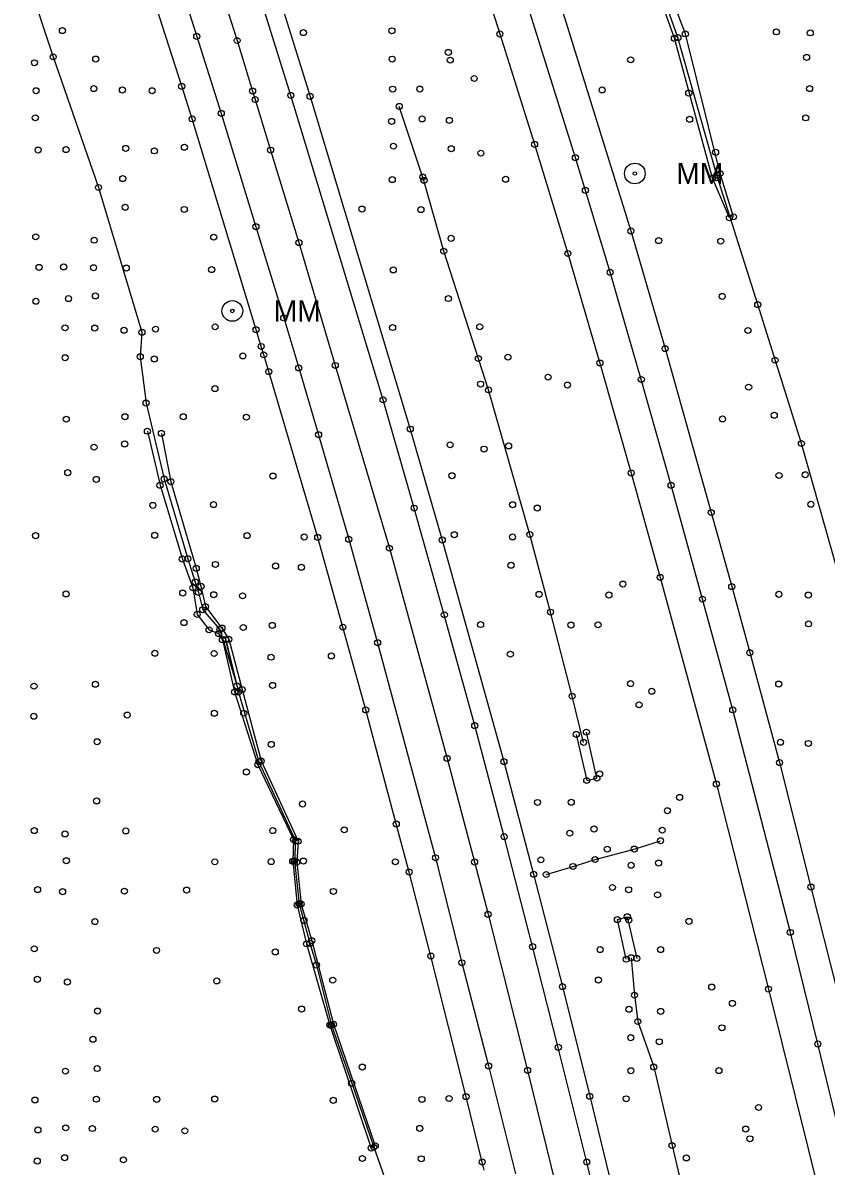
# Model space of a CAD drawing. Extents: x 20503438 to 20508873, y 7964251 to 7984667.
# Drawn here: x 20506329.2 to 20506595.4, y 7974717.9 to 7975096.9 of the extents above; entities that cross this region are included whole.
import ezdxf

# ---------------------------------------------------------------- set-up
doc = ezdxf.new("R2010")
doc.units = 0
for name, color, linetype in [('SurBreakLine', 7, 'Continuous'), ('SurConcreteSlab', 7, 'Continuous'), ('SurDrainageArrowDown', 7, 'Continuous'), ('SurDrainageArrowUp', 7, 'Continuous'), ('SurEdgeRoadPaved', 7, 'Continuous'), ('SurEdgeShoulderPaved', 7, 'Continuous'), ('SurPointsNonDTM', 7, 'Continuous'), ('SurRoadPoints', 7, 'Continuous'), ('SurSurveyPoints', 7, 'Continuous')]:
    doc.layers.add(name, color=color, linetype=linetype)

msp = doc.modelspace()

# ---------------------------------------------------------------- linework, layer by layer
at = {"layer": 'SurBreakLine'}
for points in [[(20506349.14, 7975482.98), (20506362.94, 7975447.73), (20506373.06, 7975421.29), (20506389.9, 7975376.81), (20506416.68, 7975304.59), (20506442.42, 7975230.98), (20506465.81, 7975160.63), (20506487.25, 7975093.26), (20506498.75, 7975056.68), (20506509.78, 7975020.48), (20506520.41, 7974984.15), (20506530.78, 7974947.69), (20506540.38, 7974913.1), (20506559, 7974844.57), (20506576.27, 7974776.6), (20506593.8, 7974705.89)], [(20506563.33, 7975032.31), (20506557.73, 7975045.49), (20506545.09, 7975091.83), (20506536.07, 7975117.23), (20506528.64, 7975137.21), (20506513.06, 7975181.68), (20506498.04, 7975232.83), (20506490.75, 7975254.66), (20506483.47, 7975281.58), (20506478.73, 7975292.65), (20506472.08, 7975308.47), (20506471.96, 7975323.59)], [(20506564.68, 7975032.65), (20506560.23, 7975047), (20506548.72, 7975093.3), (20506540.37, 7975115.26), (20506533.76, 7975140.2), (20506518.04, 7975183.5), (20506500.13, 7975235.89), (20506493.28, 7975255.12), (20506484.64, 7975281.71), (20506485.6, 7975286.88), (20506482.64, 7975294.9), (20506475.18, 7975312.04), (20506473.09, 7975324.52)], [(20506389.28, 7975125.26), (20506400.17, 7975091.1), (20506405.3, 7975074.33), (20506406.15, 7975071.53), (20506411.27, 7975054.76), (20506420.66, 7975024.09), (20506432.71, 7974983.37), (20506450.65, 7974922.79), (20506469.75, 7974853.08), (20506478.86, 7974818.75), (20506483.33, 7974801.41), (20506496.44, 7974749.65), (20506513.28, 7974680.82)], [(20506370.42, 7974961.57), (20506374.61, 7974943.64), (20506382.01, 7974919.2), (20506385.5, 7974909.64), (20506386.94, 7974900.83), (20506390.87, 7974895.72), (20506394.03, 7974894.48), (20506395.3, 7974892.44), (20506399.35, 7974875.13), (20506407.04, 7974851), (20506418.84, 7974826.2), (20506418.61, 7974818.98), (20506420.12, 7974804.45), (20506423.15, 7974791.61), (20506430.93, 7974764.69), (20506444.62, 7974723.91)], [(20506375.08, 7974960.84), (20506378.21, 7974944.81), (20506386.64, 7974916.14), (20506388.19, 7974910.14), (20506389.67, 7974903.41), (20506395.13, 7974896.31), (20506397.4, 7974892.6), (20506401.84, 7974875.91), (20506408.1, 7974852.25), (20506420.39, 7974825.64), (20506419.97, 7974818.7), (20506421.36, 7974804.8), (20506424.88, 7974792.66), (20506432.12, 7974764.97), (20506445.95, 7974724.65)], [(20506502.61, 7974814.6), (20506511.49, 7974817.27), (20506518.79, 7974819.57), (20506531.8, 7974823.05), (20506540.49, 7974825.8)]]:
    msp.add_lwpolyline(points, dxfattribs=at)
at = {"layer": 'SurConcreteSlab'}
for points in [[(20506512.57, 7974861.04), (20506516.05, 7974845.77), (20506519.41, 7974846.53), (20506515.93, 7974861.8)], [(20506529.15, 7974786.52), (20506526.21, 7974799.66), (20506529.49, 7974800.59), (20506532.6, 7974786.79)]]:
    msp.add_lwpolyline(points, dxfattribs=at)
at = {"layer": 'SurDrainageArrowDown'}
for points in [[(20506657.71, 7974715.84), (20506642.35, 7974760.13), (20506632.42, 7974809.79), (20506615.88, 7974859.7), (20506600.79, 7974909.51), (20506587.18, 7974957.49), (20506572.7, 7975003.54), (20506559.2, 7975046.45), (20506546.26, 7975092.07), (20506538.01, 7975115.31)], [(20506514.97, 7974858.39), (20506511.2, 7974873.72), (20506504.04, 7974901.59), (20506497.18, 7974927.32), (20506483.49, 7974975.27), (20506468.65, 7975021.25), (20506462.1, 7975044.71), (20506453.91, 7975069.27)]]:
    msp.add_lwpolyline(points, dxfattribs=at)
at = {"layer": 'SurDrainageArrowUp'}
for points in [[(20506330.76, 7975111.05), (20506339.21, 7975085.68), (20506354.22, 7975042.36), (20506368.61, 7974994.38), (20506368.05, 7974986.26), (20506369.98, 7974970.9), (20506375.98, 7974945.73), (20506383.84, 7974919.28), (20506386.3, 7974911.54), (20506387.33, 7974908.1), (20506388.76, 7974902.36), (20506394.43, 7974895.84), (20506400.13, 7974877.07), (20506396.37, 7974892.43), (20506400.64, 7974875.1), (20506407.39, 7974851.97), (20506419.55, 7974825.72), (20506419.14, 7974819.06), (20506420.69, 7974804.93), (20506424.29, 7974791.81), (20506426.47, 7974784.56), (20506431.41, 7974764.69), (20506438.13, 7974745.38), (20506445.47, 7974724.2), (20506449.66, 7974712.24)], [(20506530.75, 7974787.02), (20506531.86, 7974774.59), (20506532.96, 7974765.86), (20506538.23, 7974750.79), (20506544.31, 7974724.75), (20506550.52, 7974698.23), (20506555.49, 7974671.16), (20506562.9, 7974645.49), (20506569.02, 7974618.1), (20506580.96, 7974569.62)]]:
    msp.add_lwpolyline(points, dxfattribs=at)
at = {"layer": 'SurEdgeRoadPaved'}
for points in [[(20506532.64, 7974648.96), (20506516.06, 7974719.27), (20506506.62, 7974757.3), (20506498.09, 7974790.71), (20506488.67, 7974827.17), (20506478.91, 7974863.97), (20506468.84, 7974900.69), (20506458.86, 7974936.07), (20506448.53, 7974971.96), (20506417.96, 7975072.9), (20506405.34, 7975113.32), (20506382.6, 7975182.03), (20506369.4, 7975220.83), (20506345.88, 7975288.32), (20506331.62, 7975327.71), (20506320.36, 7975358.51), (20506306.95, 7975393.79), (20506278.91, 7975465.84), (20506257.71, 7975518.12)], [(20506367.4, 7975497.02), (20506382.84, 7975458.29), (20506396.34, 7975422.39), (20506402.33, 7975406.46), (20506419.54, 7975360.34), (20506427.81, 7975337.94), (20506435.05, 7975318.28), (20506442.77, 7975296.67), (20506447.6, 7975283.16), (20506459.75, 7975248.31), (20506474.87, 7975203.27), (20506484.19, 7975175.26), (20506494.28, 7975143.45), (20506508.53, 7975099.05), (20506530.67, 7975027.95), (20506542.03, 7974988.95), (20506557.31, 7974934.61), (20506564.1, 7974910.06), (20506570.08, 7974888.15), (20506579.93, 7974851.7), (20506590.35, 7974810.45), (20506601.11, 7974767.59), (20506615.26, 7974710.46)], [(20506247.96, 7975479.81), (20506260.54, 7975448.2), (20506275.43, 7975410.2), (20506290.26, 7975371.02), (20506301.37, 7975341.22), (20506312.67, 7975310.54), (20506324.74, 7975277.04), (20506349.3, 7975206.77), (20506372.83, 7975136.5), (20506386.78, 7975092.48), (20506394.92, 7975066.92), (20506406.39, 7975029.37), (20506415.61, 7974999.14), (20506420.57, 7974982.55), (20506427.17, 7974960.41), (20506437.15, 7974925.73), (20506446.74, 7974891.45), (20506465.93, 7974820.14), (20506474.65, 7974785.33), (20506483.51, 7974751.12), (20506492.4, 7974715.32)], [(20506618.24, 7974651.55), (20506601.4, 7974722.56), (20506592.63, 7974758.41), (20506583.52, 7974795.39), (20506564.42, 7974869.18), (20506554.39, 7974905.89), (20506543.98, 7974943.66), (20506534.13, 7974978.72), (20506523.8, 7975014.27), (20506515.58, 7975041.4), (20506512.29, 7975052.25), (20506490.77, 7975121.09), (20506467.72, 7975192.09), (20506455.87, 7975227.47), (20506443.11, 7975264.71), (20506430.35, 7975301.25), (20506417.72, 7975336.15), (20506403.48, 7975374.04), (20506389.38, 7975412.58), (20506375.71, 7975448.39), (20506362.64, 7975481.5)], [(20506482.06, 7974716.57), (20506481.39, 7974719.26), (20506476.04, 7974740.93), (20506464.38, 7974787.55), (20506457.19, 7974815.4), (20506452.9, 7974831.37), (20506442.78, 7974869.15), (20506435.21, 7974896.61), (20506426.88, 7974926.37), (20506410.66, 7974981.33), (20506408.98, 7974986.89), (20506408.14, 7974989.67), (20506406.46, 7974995.22), (20506385.25, 7975065.12), (20506381.79, 7975075.91), (20506371.23, 7975109.03)]]:
    msp.add_lwpolyline(points, dxfattribs=at)
at = {"layer": 'SurEdgeShoulderPaved'}
msp.add_lwpolyline([(20506267.06, 7975511.74), (20506296.53, 7975437.96), (20506310.81, 7975400.98), (20506324.27, 7975365.52), (20506351.09, 7975291.82), (20506363.94, 7975255.58), (20506381.4, 7975204.73), (20506388.98, 7975182.4), (20506412.98, 7975109.14), (20506424.35, 7975072.59), (20506457.56, 7974962.26), (20506468.15, 7974925.5), (20506488.59, 7974852.02), (20506498.44, 7974814.69), (20506507.99, 7974777.45), (20506517.02, 7974741.08), (20506525.96, 7974704.19)], dxfattribs=at)
at = {"layer": 'SurPointsNonDTM'}
msp.add_circle((20506522.84, 7974823.01), 1, dxfattribs=at)
at = {"layer": 'SurRoadPoints'}
for centre, radius in [((20506531.98, 7975047.01), 3.43), ((20506531.98, 7975047.01), 0.571), ((20506398.58, 7975001.43), 3.43), ((20506398.58, 7975001.43), 0.571)]:
    msp.add_circle(centre, radius, dxfattribs=at)
at = {"layer": 'SurSurveyPoints'}
for centre in [(20506342.27, 7975094.38), (20506386.78, 7975092.48), (20506422.12, 7975093.72), (20506451.46, 7975094.32), (20506487.25, 7975093.26), (20506545.09, 7975091.83), (20506546.26, 7975092.07), (20506548.72, 7975093.3), (20506578.9, 7975093.96), (20506590.12, 7975093.63), (20506400.17, 7975091.1), (20506333, 7975083.71), (20506339.21, 7975085.68), (20506353.29, 7975084.95), (20506451.54, 7975084.93), (20506470.17, 7975087.17), (20506470.82, 7975084.59), (20506530.6, 7975084.7), (20506588.91, 7975085.5), (20506478.74, 7975078.51), (20506333.56, 7975074.46), (20506352.67, 7975075.16), (20506362.15, 7975074.69), (20506372, 7975074.44), (20506381.79, 7975075.91), (20506405.3, 7975074.33), (20506417.96, 7975072.9), (20506424.35, 7975072.59), (20506451.72, 7975074.98), (20506460.71, 7975075), (20506521.14, 7975074.72), (20506549.84, 7975073.66), (20506589.89, 7975075.16), (20506406.15, 7975071.53), (20506453.91, 7975069.27), (20506333.29, 7975065.47), (20506385.25, 7975065.12), (20506394.92, 7975066.92), (20506461.48, 7975065.11), (20506550.13, 7975064.98), (20506588.63, 7975065.45), (20506451.36, 7975064.29), (20506470.53, 7975064.62), (20506334.22, 7975054.77), (20506343.48, 7975054.93), (20506363.25, 7975055.33), (20506372.74, 7975054.51), (20506382.7, 7975055.7), (20506411.27, 7975054.76), (20506451.99, 7975056.06), (20506471.14, 7975055.21), (20506480.95, 7975053.76), (20506498.75, 7975056.68), (20506558.74, 7975054.02), (20506512.29, 7975052.25), (20506461.71, 7975045.83), (20506559.2, 7975046.45), (20506560.23, 7975047), (20506354.22, 7975042.36), (20506362.25, 7975045.33), (20506451.6, 7975044.98), (20506462.1, 7975044.71), (20506489.16, 7975045.09), (20506557.73, 7975045.49), (20506559.03, 7975045.59), (20506515.58, 7975041.4), (20506363.07, 7975035.8), (20506382.66, 7975035.09), (20506441.52, 7975035.22), (20506461.1, 7975035.03), (20506563.33, 7975032.31), (20506564.68, 7975032.65), (20506406.39, 7975029.37), (20506530.67, 7975027.95), (20506333.43, 7975026.01), (20506352.8, 7975024.89), (20506392.4, 7975025.91), (20506420.66, 7975024.09), (20506471.1, 7975025.51), (20506539.88, 7975024.75), (20506560.45, 7975024.57), (20506468.65, 7975021.25), (20506509.78, 7975020.48), (20506334.53, 7975015.87), (20506342.68, 7975016.02), (20506352.58, 7975015.76), (20506363.44, 7975015.65), (20506391.73, 7975015.15), (20506451.92, 7975015.03), (20506523.8, 7975014.27), (20506333.46, 7975004.64), (20506344.28, 7975005.53), (20506353.2, 7975006.41), (20506470.19, 7975005.55), (20506560.94, 7975006.25), (20506572.7, 7975003.54), (20506415.61, 7974999.14), (20506343.12, 7974995.83), (20506352.97, 7974995.75), (20506362.71, 7974995.03), (20506368.61, 7974994.38), (20506373.12, 7974995.41), (20506392.88, 7974996.18), (20506406.46, 7974995.22), (20506451.7, 7974995.94), (20506480.58, 7974996.18), (20506569.45, 7974994.96), (20506408.14, 7974989.67), (20506542.03, 7974988.95), (20506343.17, 7974985.92), (20506368.05, 7974986.26), (20506372.69, 7974985.54), (20506402.07, 7974986.54), (20506408.98, 7974986.89), (20506480.12, 7974985.67), (20506489.92, 7974986.12), (20506420.57, 7974982.55), (20506432.71, 7974983.37), (20506520.41, 7974984.15), (20506578.46, 7974985.12), (20506410.66, 7974981.33), (20506503.25, 7974979.49), (20506534.13, 7974978.72), (20506392.8, 7974975.68), (20506480.87, 7974977.18), (20506483.49, 7974975.27), (20506509.65, 7974976.86), (20506569.71, 7974976.17), (20506369.98, 7974970.9), (20506448.53, 7974971.96), (20506362.99, 7974966.36), (20506382.32, 7974966.36), (20506403.25, 7974966.22), (20506578.19, 7974966.85), (20506343.54, 7974965.55), (20506561.05, 7974965.63), (20506370.42, 7974961.57), (20506375.08, 7974960.84), (20506427.17, 7974960.41), (20506457.56, 7974962.26), (20506352.75, 7974956.28), (20506362.9, 7974957.34), (20506470.76, 7974957.06), (20506482.02, 7974955.63), (20506490.15, 7974956.69), (20506587.18, 7974957.49), (20506344.03, 7974947.82), (20506530.78, 7974947.69), (20506353.47, 7974945.6), (20506374.61, 7974943.64), (20506375.98, 7974945.73), (20506378.21, 7974944.81), (20506412.04, 7974946.7), (20506471.37, 7974946.81), (20506543.98, 7974943.66), (20506579.76, 7974946.89), (20506588.45, 7974947.15), (20506372.23, 7974936.97), (20506392.35, 7974937.24), (20506458.86, 7974936.07), (20506491.46, 7974937.18), (20506499.63, 7974936.08), (20506590.32, 7974937.36), (20506557.31, 7974934.61), (20506333.38, 7974926.94), (20506372.86, 7974927.06), (20506403.47, 7974926.96), (20506422.4, 7974926.49), (20506426.88, 7974926.37), (20506437.15, 7974925.73), (20506468.15, 7974925.5), (20506472.15, 7974927.26), (20506491.44, 7974926.52), (20506497.18, 7974927.32), (20506450.65, 7974922.79), (20506382.01, 7974919.2), (20506383.84, 7974919.28), (20506392.98, 7974917.39), (20506490.94, 7974917.13), (20506386.64, 7974916.14), (20506412.92, 7974916.89), (20506421.47, 7974916.47), (20506385.5, 7974909.64), (20506386.3, 7974911.54), (20506388.19, 7974910.14), (20506528.01, 7974910.89), (20506540.38, 7974913.1), (20506564.1, 7974910.06), (20506343.48, 7974907.61), (20506382.15, 7974907.92), (20506387.33, 7974908.1), (20506392.42, 7974907.37), (20506401.99, 7974906.99), (20506500.25, 7974907.45), (20506523.39, 7974907.27), (20506554.39, 7974905.89), (20506579.71, 7974907.49), (20506589.48, 7974907.26), (20506388.76, 7974902.36), (20506389.67, 7974903.41), (20506382.54, 7974898.12), (20506386.94, 7974900.83), (20506468.84, 7974900.69), (20506504.04, 7974901.59), (20506390.87, 7974895.72), (20506394.03, 7974894.48), (20506394.43, 7974895.84), (20506395.13, 7974896.31), (20506402.19, 7974896.49), (20506411.81, 7974897.2), (20506435.21, 7974896.61), (20506480.87, 7974897.47), (20506510.8, 7974897.29), (20506519.78, 7974897.37), (20506589.55, 7974897.69), (20506395.3, 7974892.44), (20506396.37, 7974892.43), (20506397.4, 7974892.6), (20506446.74, 7974891.45), (20506372.9, 7974887.95), (20506392.54, 7974887.87), (20506411.43, 7974886.64), (20506431.42, 7974887.05), (20506490.72, 7974887.64), (20506570.08, 7974888.15), (20506332.85, 7974877.04), (20506353.2, 7974877.67), (20506400.13, 7974877.07), (20506401.84, 7974875.91), (20506411.92, 7974877.3), (20506530.56, 7974877.88), (20506537.6, 7974875.34), (20506579.67, 7974877.73), (20506399.35, 7974875.13), (20506400.64, 7974875.1), (20506511.2, 7974873.72), (20506392.62, 7974868.07), (20506402.37, 7974868.08), (20506442.78, 7974869.15), (20506533.38, 7974870.86), (20506564.42, 7974869.18), (20506332.78, 7974867.06), (20506363.74, 7974867.46), (20506478.91, 7974863.97), (20506512.57, 7974861.04), (20506515.93, 7974861.8), (20506353.77, 7974858.61), (20506411.47, 7974857.73), (20506514.97, 7974858.39), (20506580.25, 7974858.45), (20506589.52, 7974858.05), (20506469.75, 7974853.08), (20506407.04, 7974851), (20506407.39, 7974851.97), (20506408.1, 7974852.25), (20506488.59, 7974852.02), (20506579.93, 7974851.7), (20506403.25, 7974848.59), (20506516.05, 7974845.77), (20506519.41, 7974846.53), (20506520.29, 7974847.96), (20506559, 7974844.57), (20506353.6, 7974838.98), (20506421.84, 7974837.98), (20506499.73, 7974838.49), (20506510.91, 7974838.56), (20506546.83, 7974840.15), (20506542.79, 7974835.74), (20506452.9, 7974831.37), (20506332.93, 7974829.15), (20506343.14, 7974828.06), (20506363.28, 7974829.06), (20506411.99, 7974829.14), (20506418.84, 7974826.2), (20506435.69, 7974829.4), (20506488.67, 7974827.17), (20506510.43, 7974828.3), (20506518.45, 7974829.69), (20506541.05, 7974829.29), (20506419.55, 7974825.72), (20506420.39, 7974825.64), (20506531.8, 7974823.05), (20506540.49, 7974825.8), (20506343.56, 7974819.17), (20506392.78, 7974818.8), (20506411.45, 7974818.89), (20506418.61, 7974818.98), (20506419.14, 7974819.06), (20506419.97, 7974818.7), (20506422.14, 7974819.06), (20506452.63, 7974818.81), (20506465.93, 7974820.14), (20506478.86, 7974818.75), (20506500.83, 7974819.47), (20506518.79, 7974819.57), (20506539.86, 7974818.4), (20506457.19, 7974815.4), (20506498.44, 7974814.69), (20506502.61, 7974814.6), (20506511.49, 7974817.27), (20506530.75, 7974817.66), (20506334.04, 7974809.59), (20506342.33, 7974808.91), (20506362.82, 7974809.07), (20506383.41, 7974809.44), (20506432.07, 7974808.98), (20506524.57, 7974810.3), (20506529.91, 7974809.53), (20506539.54, 7974807.86), (20506590.35, 7974810.45), (20506420.12, 7974804.45), (20506420.69, 7974804.93), (20506421.36, 7974804.8), (20506483.33, 7974801.41), (20506526.21, 7974799.66), (20506529.49, 7974800.59), (20506529.99, 7974799.51), (20506353.02, 7974798.99), (20506422.31, 7974799.37), (20506549.9, 7974799.05), (20506424.88, 7974792.66), (20506583.52, 7974795.39), (20506332.93, 7974789.96), (20506373.46, 7974789.42), (20506412.8, 7974788.94), (20506423.15, 7974791.61), (20506424.29, 7974791.81), (20506498.09, 7974790.71), (20506520.48, 7974789.69), (20506540.53, 7974789.69), (20506426.47, 7974784.56), (20506464.38, 7974787.55), (20506474.65, 7974785.33), (20506529.15, 7974786.52), (20506530.75, 7974787.02), (20506532.6, 7974786.79), (20506333.98, 7974779.85), (20506343.93, 7974778.96), (20506393.43, 7974779.32), (20506431.86, 7974779.57), (20506507.99, 7974777.45), (20506519.89, 7974779.59), (20506557.46, 7974777.29), (20506531.86, 7974774.59), (20506576.27, 7974776.6), (20506353.9, 7974769.34), (20506421.53, 7974770), (20506530.02, 7974769.93), (20506540.54, 7974769.2), (20506564.33, 7974771.87), (20506532.96, 7974765.86), (20506430.93, 7974764.69), (20506431.41, 7974764.69), (20506432.12, 7974764.97), (20506560.85, 7974763.78), (20506352.37, 7974759.96), (20506530.65, 7974760.5), (20506540.09, 7974759.14), (20506592.63, 7974758.41), (20506506.62, 7974757.3), (20506353.77, 7974750.27), (20506441.64, 7974750.77), (20506483.51, 7974751.12), (20506538.23, 7974750.79), (20506343.27, 7974749.41), (20506496.44, 7974749.65), (20506530.66, 7974749.53), (20506559.85, 7974749.59), (20506438.13, 7974745.38), (20506333.17, 7974739.82), (20506353.54, 7974740.1), (20506373.5, 7974740.03), (20506392.75, 7974740.16), (20506432.02, 7974739.73), (20506461.42, 7974740.02), (20506470.4, 7974740.34), (20506476.04, 7974740.93), (20506517.02, 7974741.08), (20506529.12, 7974740.24), (20506572.97, 7974737.36), (20506334.14, 7974729.92), (20506343.37, 7974730.61), (20506352.18, 7974730.38), (20506373.02, 7974730.18), (20506382.84, 7974729.62), (20506460.68, 7974730.42), (20506568.75, 7974730.22), (20506444.62, 7974723.91), (20506445.47, 7974724.2), (20506445.95, 7974724.65), (20506544.31, 7974724.75), (20506570.14, 7974726.98), (20506342.98, 7974720.7), (20506362.48, 7974720), (20506441.7, 7974720.45), (20506461.2, 7974720.35), (20506549.05, 7974720.64), (20506333.94, 7974719.61), (20506481.39, 7974719.26), (20506516.06, 7974719.27)]:
    msp.add_circle(centre, 1, dxfattribs=at)

# ---------------------------------------------------------------- texts
at = {"layer": 'SurRoadPoints'}
for p in [(20506545.69, 7975043.52), (20506412.29, 7974997.94)]:
    msp.add_text('MM', height=6.995, rotation=360, dxfattribs=at).set_placement(p)

doc.saveas('drawing.dxf')
